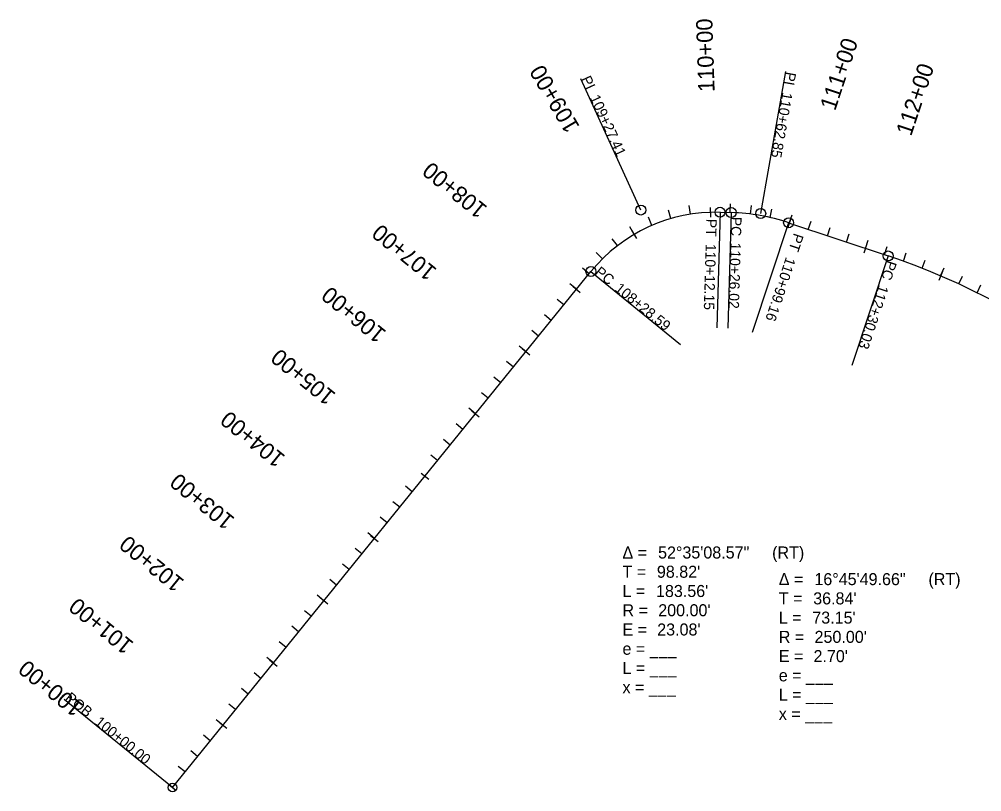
# Model space of a CAD drawing. Extents: x 14106984 to 14110066, y 8637277 to 8639226.
# Drawn here: x 14106984 to 14108185, y 8638263 to 8639226 of the extents above; entities that cross this region are included whole.
import ezdxf

# ---------------------------------------------------------------- set-up
doc = ezdxf.new("R2010")
doc.units = 0
for name, color, linetype in [('Alignment', 7, 'Continuous'), ('Default', 7, 'Continuous'), ('TextAlignment', 7, 'Continuous'), ('TextAlignmentLrg', 7, 'Continuous'), ('TextAlignmentSml', 7, 'Continuous')]:
    doc.layers.add(name, color=color, linetype=linetype)

msp = doc.modelspace()

# ---------------------------------------------------------------- linework, layer by layer
at = {"layer": 'Alignment'}
for p, q in [((14107858.4, 8638985.7), (14107872.3, 8638985.3)), ((14107944, 8638972.6), (14108068.2, 8638931.2)), ((14107175.2, 8638268.4), (14107697.4, 8638911.8))]:
    msp.add_line(p, q, dxfattribs=at)
for centre, radius, start, end in [((14107852.7, 8638785.7), 200, 88.3518, 140.9375), ((14107865.1, 8638735.4), 250, 71.588, 88.3518), ((14107799.7, 8638124.7), 850, 31.0039, 71.588)]:
    msp.add_arc(centre, radius, start, end, dxfattribs=at)
at = {"layer": 'Default'}
for p, q in [((14107858.4, 8638985.7), (14107872.3, 8638985.3)), ((14107944, 8638972.6), (14108068.2, 8638931.2)), ((14107175.2, 8638268.4), (14107697.4, 8638911.8))]:
    msp.add_line(p, q, dxfattribs=at)
for centre, radius, start, end in [((14107852.7, 8638785.7), 200, 88.3518, 140.9375), ((14107865.1, 8638735.4), 250, 71.588, 88.3518), ((14107799.7, 8638124.7), 850, 31.0039, 71.588)]:
    msp.add_arc(centre, radius, start, end, dxfattribs=at)
at = {"layer": 'TextAlignment'}
for p, q in [((14107909.1, 8638984.2), (14107940.4, 8639161.4)), ((14107759.6, 8638988.5), (14107684.6, 8639152.1)), ((14107858.4, 8638985.7), (14107854.3, 8638841.7)), ((14107872.3, 8638985.3), (14107868.1, 8638841.3)), ((14107944, 8638972.6), (14107898.6, 8638835.9)), ((14108068.2, 8638931.2), (14108022.7, 8638794.6)), ((14107697.4, 8638911.8), (14107809.2, 8638821)), ((14107175.2, 8638268.4), (14107040.1, 8638378))]:
    msp.add_line(p, q, dxfattribs=at)
for centre, radius in [((14107759.6, 8638988.5), 6.24), ((14107858.4, 8638985.7), 6.24), ((14107872.3, 8638985.3), 6.24), ((14107909.1, 8638984.2), 6.24), ((14107917.5, 8638979.8), 0.05), ((14107944, 8638972.6), 6.24), ((14107782, 8638972.8), 0.05), ((14108068.2, 8638931.2), 6.24), ((14107697.4, 8638911.8), 6.24), ((14107175.2, 8638268.4), 5.34)]:
    msp.add_circle(centre, radius, dxfattribs=at)
at = {"layer": 'TextAlignmentLrg'}
for p, q in [((14107846.1, 8638991.7), (14107846.4, 8638979.5)), ((14107944.8, 8638972.3), (14107948.3, 8638982.7)), ((14107751.2, 8638958.1), (14107745.7, 8638967.5)), ((14108039.7, 8638940.7), (14108043.2, 8638951.1)), ((14108133.6, 8638906.4), (14108137.9, 8638916.5)), ((14107679.3, 8638889.6), (14107670.9, 8638896.4)), ((14107616.3, 8638811.9), (14107607.8, 8638818.8)), ((14107553.3, 8638734.3), (14107544.8, 8638741.2)), ((14107485.5, 8638660.5), (14107495, 8638652.8)), ((14107427.3, 8638579), (14107418.8, 8638585.9)), ((14107364.3, 8638501.3), (14107355.8, 8638508.2)), ((14107301.2, 8638423.7), (14107292.8, 8638430.6)), ((14107238.2, 8638346), (14107229.7, 8638352.9)), ((14107170.5, 8638272.3), (14107180, 8638264.5))]:
    msp.add_line(p, q, dxfattribs=at)
at = {"layer": 'TextAlignmentSml'}
for p, q in [((14107821.4, 8638983.3), (14107819.7, 8638994.1)), ((14107846.1, 8638991.7), (14107846.4, 8638979.5)), ((14107871.2, 8638985.3), (14107871.6, 8638996.2)), ((14107896.2, 8638983.4), (14107897.5, 8638994.2)), ((14107773.5, 8638969.4), (14107769.2, 8638979.4)), ((14107797, 8638977.8), (14107794, 8638988.3)), ((14107920.8, 8638979.1), (14107923.2, 8638989.7)), ((14107946.8, 8638978.1), (14107942.9, 8638966.5)), ((14107968.5, 8638964.4), (14107972, 8638974.8)), ((14107992.3, 8638956.5), (14107995.7, 8638966.9)), ((14107748.1, 8638963.4), (14107754.3, 8638952.8)), ((14108016, 8638948.6), (14108019.4, 8638959)), ((14107730.5, 8638944.1), (14107723.8, 8638952.7)), ((14108041.6, 8638946.5), (14108037.8, 8638934.9)), ((14108063.4, 8638932.8), (14108066.9, 8638943.2)), ((14107711.7, 8638927.6), (14107704, 8638935.4)), ((14108087.1, 8638924.7), (14108090.8, 8638935)), ((14108110.5, 8638915.9), (14108114.5, 8638926.1)), ((14107695.1, 8638909), (14107686.6, 8638915.9)), ((14108136, 8638912), (14108131.2, 8638900.8)), ((14108156.4, 8638896.3), (14108161, 8638906.2)), ((14108179, 8638885.4), (14108183.9, 8638895.2)), ((14107674.6, 8638893.4), (14107684.1, 8638885.7)), ((14107663.6, 8638870.2), (14107655.1, 8638877)), ((14107647.8, 8638850.7), (14107639.4, 8638857.6)), ((14107632.1, 8638831.3), (14107623.6, 8638838.2)), ((14107611.6, 8638815.8), (14107621.1, 8638808.1)), ((14107600.6, 8638792.5), (14107592.1, 8638799.4)), ((14107584.8, 8638773.1), (14107576.3, 8638780)), ((14107569.1, 8638753.7), (14107560.6, 8638760.6)), ((14107548.6, 8638738.1), (14107558.1, 8638730.4)), ((14107537.6, 8638714.9), (14107529.1, 8638721.7)), ((14107521.8, 8638695.4), (14107513.3, 8638702.3)), ((14107506, 8638676), (14107497.6, 8638682.9)), ((14107485.5, 8638660.5), (14107495, 8638652.8)), ((14107474.5, 8638637.2), (14107466.1, 8638644.1)), ((14107458.8, 8638617.8), (14107450.3, 8638624.7)), ((14107443, 8638598.4), (14107434.5, 8638605.3)), ((14107422.5, 8638582.8), (14107432, 8638575.1)), ((14107411.5, 8638559.6), (14107403, 8638566.5)), ((14107395.8, 8638540.2), (14107387.3, 8638547)), ((14107380, 8638520.7), (14107371.5, 8638527.6)), ((14107359.5, 8638505.2), (14107369, 8638497.5)), ((14107348.5, 8638481.9), (14107340, 8638488.8)), ((14107332.7, 8638462.5), (14107324.3, 8638469.4)), ((14107317, 8638443.1), (14107308.5, 8638450)), ((14107296.5, 8638427.5), (14107306, 8638419.8)), ((14107285.5, 8638404.3), (14107277, 8638411.2)), ((14107269.7, 8638384.9), (14107261.3, 8638391.7)), ((14107254, 8638365.5), (14107245.5, 8638372.3)), ((14107233.5, 8638349.9), (14107243, 8638342.2)), ((14107222.5, 8638326.6), (14107214, 8638333.5)), ((14107206.7, 8638307.2), (14107198.2, 8638314.1)), ((14107191, 8638287.8), (14107182.5, 8638294.7)), ((14107170.5, 8638272.3), (14107180, 8638264.5))]:
    msp.add_line(p, q, dxfattribs=at)

# ---------------------------------------------------------------- texts
at = {"layer": 'TextAlignment'}
for s, rotation, p in [('PI ', 259.9699, (14107940.7, 8639161.4)), ('PI ', 294.6446, (14107684.8, 8639152.2)), ('109+27.41', 294.6446, (14107695.6, 8639128.7)), ('110+62.85', 259.9699, (14107936.2, 8639136)), ('PC', 268.3518, (14107872.4, 8638980.2)), ('PT', 268.3518, (14107841.4, 8638977.7)), ('PT', 251.588, (14107950.7, 8638960.4)), ('110+12.15', 268.3518, (14107840.5, 8638946.4)), ('110+26.02', 268.3518, (14107871.4, 8638948)), ('110+99.16', 251.588, (14107940.8, 8638930.6)), ('PC', 251.588, (14108066.9, 8638926.5)), ('PC', 320.9375, (14107701.1, 8638909.1)), ('108+28.59', 320.9375, (14107726.1, 8638888.7)), ('112+30.03', 251.588, (14108056.7, 8638895.9)), ('POB ', 320.9375, (14107040.3, 8638378.2)), ('100+00.00', 320.9375, (14107077.4, 8638348.1))]:
    msp.add_text(s, height=12.96, rotation=rotation, dxfattribs=at).set_placement(p)
for s, p in [('Δ = ', (14107736.7, 8638553.9)), ('52°35\'08.57"', (14107781.1, 8638553.9)), (' (RT)', (14107917.8, 8638553.9)), ('T = ', (14107736.7, 8638529.9)), ("98.82'", (14107779.6, 8638529.9)), ('Δ = ', (14107931.7, 8638520.7)), ('16°45\'49.66"', (14107976.1, 8638520.7)), (' (RT)', (14108112.8, 8638520.7)), ('L = ', (14107736.7, 8638505.9)), ("183.56'", (14107778.5, 8638505.9)), ('T = ', (14107931.7, 8638496.7)), ("36.84'", (14107974.6, 8638496.7)), ('R = ', (14107736.7, 8638481.9)), ("200.00'", (14107781.3, 8638481.9)), ('L = ', (14107931.7, 8638472.7)), ("73.15'", (14107973.5, 8638472.7)), ('E = ', (14107736.7, 8638457.9)), ("23.08'", (14107780, 8638457.9)), ('R = ', (14107931.7, 8638448.7)), ("250.00'", (14107976.3, 8638448.7)), ('e = ___ ', (14107736.7, 8638433.9)), ('E = ', (14107931.7, 8638424.7)), ("2.70'", (14107975, 8638424.7)), ('L = ___', (14107736.7, 8638409.9)), ('e = ___ ', (14107931.7, 8638400.7)), ('x = ___', (14107736.7, 8638385.9)), ('L = ___', (14107931.7, 8638376.7)), ('x = ___', (14107931.7, 8638352.7))]:
    msp.add_text(s, height=15, dxfattribs=at).set_placement(p)
at = {"layer": 'TextAlignmentLrg'}
for s, rotation, p in [('110+00', 91.8332, (14107851.7, 8639135.9)), ('105+00', 140.9375, (14107380.2, 8638759.1)), ('100+00', 140.9375, (14107065.2, 8638370.8))]:
    msp.add_text(s, height=20.4, rotation=rotation, dxfattribs=at).set_placement(p)
at = {"layer": 'TextAlignmentSml'}
for s, rotation, p in [('110+00', 91.8332, (14107851.7, 8639135.9)), ('111+00', 71.588, (14108001.9, 8639111.4)), ('109+00', 120.4811, (14107683.9, 8639092.5)), ('112+00', 71.588, (14108096.8, 8639079.8)), ('108+00', 140.9375, (14107569.3, 8638992)), ('107+00', 140.9375, (14107506.3, 8638914.4)), ('106+00', 140.9375, (14107443.3, 8638836.7)), ('105+00', 140.9375, (14107380.2, 8638759.1)), ('104+00', 140.9375, (14107317.2, 8638681.4)), ('103+00', 140.9375, (14107254.2, 8638603.8)), ('102+00', 140.9375, (14107191.2, 8638526.1)), ('101+00', 140.9375, (14107128.2, 8638448.5)), ('100+00', 140.9375, (14107065.2, 8638370.8))]:
    msp.add_text(s, height=20.4, rotation=rotation, dxfattribs=at).set_placement(p)

doc.saveas('drawing.dxf')
